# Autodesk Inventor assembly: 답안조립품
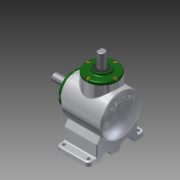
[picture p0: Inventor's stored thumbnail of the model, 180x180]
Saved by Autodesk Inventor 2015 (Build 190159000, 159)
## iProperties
Created: 2018-08
Part Number: 답안조립품
Document SubType Name: Assembly
Designer: line
Author: line
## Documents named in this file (14)
- C:\Users\line\Desktop\480807V1011\답안조립품.iam
- C:\Users\line\Desktop\480807V1011\본체.ipt
- C:\Users\line\Desktop\480807V1011\베어링 6203.ipt
- C:\Users\line\Desktop\480807V1011\오일실 17 32 8.ipt
- C:\Users\line\Desktop\480807V1011\커버.ipt
- C:\Users\line\Desktop\480807V1011\볼트 M4.ipt
- C:\Users\line\Desktop\480807V1011\서브 베벨기어.ipt
- C:\Users\line\Desktop\480807V1011\서브 축.ipt
- 서브 축.ipt
- C:\Users\line\Desktop\480807V1011\키 4x4.ipt
- C:\Users\line\Desktop\480807V1011\메인 베벨기어.ipt
- C:\Users\line\Desktop\480807V1011\메인 축.ipt
- 메인 축.ipt
- C:\Users\line\Desktop\480807V1011\키 5x5.ipt
